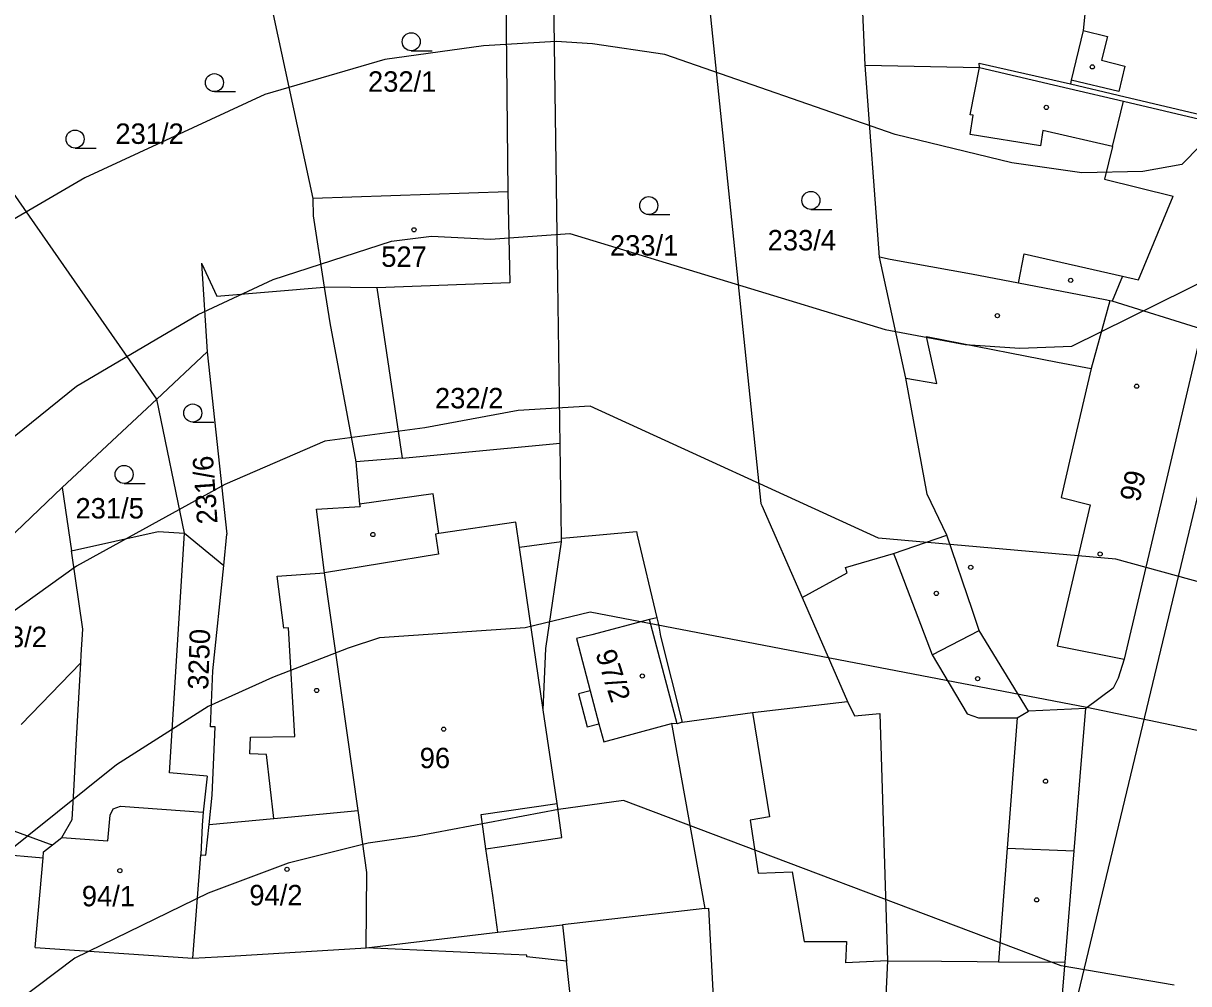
# Model space of a CAD drawing. Extents: x -555860 to -552701, y -1187050 to -1182291.
# Drawn here: x -554496.6 to -554399.7, y -1184505.6 to -1184425.7 of the extents above; entities that cross this region are included whole.
import ezdxf

# ---------------------------------------------------------------- set-up
doc = ezdxf.new("R2010")
doc.units = 0
for name, color, linetype in [('CYKLISTI_stav', 7, 'Continuous'), ('LEG_2b', 7, 'Continuous'), ('Level 25', 7, 'Continuous'), ('Level 40', 7, 'Continuous'), ('Level 41', 7, 'Continuous'), ('navrh_BV', 7, 'Continuous'), ('Poz předměty', 7, 'Continuous')]:
    doc.layers.add(name, color=color, linetype=linetype)

msp = doc.modelspace()

# ---------------------------------------------------------------- linework, layer by layer
at = {"layer": 'CYKLISTI_stav'}
for p, q in [((-554408.44, -1184426.33), (-554406.41, -1184426.85)), ((-554406.41, -1184426.85), (-554406.91, -1184428.81)), ((-554417.82, -1184433.35), (-554417.05, -1184429.41)), ((-554417.05, -1184429.41), (-554409.58, -1184431.17)), ((-554406.91, -1184428.81), (-554404.97, -1184429.3)), ((-554404.97, -1184429.3), (-554405.47, -1184431.41)), ((-554409.58, -1184431.17), (-554405.07, -1184432.23)), ((-554405.47, -1184431.41), (-554409.42, -1184430.48)), ((-554405.99, -1184436), (-554405.07, -1184432.23)), ((-554405.07, -1184432.23), (-554398.26, -1184433.83)), ((-554417.84, -1184434.99), (-554417.57, -1184433.39)), ((-554417.57, -1184433.39), (-554417.82, -1184433.35)), ((-554411.98, -1184435.93), (-554417.84, -1184434.99)), ((-554411.77, -1184434.67), (-554411.98, -1184435.93)), ((-554405.99, -1184436), (-554411.77, -1184434.67)), ((-554405.99, -1184436), (-554406.65, -1184438.71)), ((-554406.65, -1184438.71), (-554400.94, -1184440.13)), ((-554403.84, -1184447.08), (-554400.94, -1184440.13)), ((-554413.81, -1184447.35), (-554413.34, -1184444.92)), ((-554413.34, -1184444.92), (-554405.15, -1184446.78)), ((-554405.15, -1184446.78), (-554406.02, -1184448.85)), ((-554405.15, -1184446.78), (-554403.84, -1184447.08)), ((-554467.17, -1184447.74), (-554471.55, -1184447.68)), ((-554406.22, -1184448.82), (-554407.75, -1184454.46)), ((-554421.47, -1184451.8), (-554419.91, -1184452.11)), ((-554420.59, -1184455.71), (-554421.47, -1184451.8)), ((-554419.91, -1184452.11), (-554410.55, -1184453.92)), ((-554410.55, -1184453.92), (-554407.75, -1184454.46)), ((-554407.75, -1184454.46), (-554409.49, -1184461.8)), ((-554423.17, -1184455.27), (-554420.59, -1184455.71)), ((-554409.49, -1184461.8), (-554410.27, -1184465.2)), ((-554410.27, -1184465.2), (-554407.86, -1184465.79)), ((-554407.86, -1184465.79), (-554410.58, -1184477.53)), ((-554462.02, -1184468.17), (-554462.3, -1184468.23)), ((-554462.3, -1184468.23), (-554462.04, -1184469.9)), ((-554462.04, -1184469.9), (-554471.52, -1184471.45)), ((-554453.33, -1184482.86), (-554455.3, -1184469.36)), ((-554424.19, -1184469.85), (-554424.03, -1184470.27)), ((-554424.03, -1184470.27), (-554420.99, -1184478.29)), ((-554475.47, -1184471.73), (-554471.52, -1184471.45)), ((-554474.92, -1184476.07), (-554475.47, -1184471.73)), ((-554442.21, -1184484.02), (-554444.5, -1184475.35)), ((-554474.52, -1184476.02), (-554474.92, -1184476.07)), ((-554473.99, -1184485.06), (-554474.52, -1184476.02)), ((-554420.99, -1184478.29), (-554417.08, -1184476.26)), ((-554410.58, -1184477.53), (-554405.01, -1184478.65)), ((-554420.99, -1184478.29), (-554418.07, -1184483.18)), ((-554496.76, -1184484.07), (-554491.8, -1184478.94)), ((-554449.43, -1184481.26), (-554448.7, -1184484.02)), ((-554435.93, -1184483.08), (-554434.53, -1184491.76)), ((-554418.07, -1184483.18), (-554417.13, -1184483.53)), ((-554417.13, -1184483.53), (-554415.81, -1184483.52)), ((-554415.81, -1184483.52), (-554413.91, -1184483.52)), ((-554413.91, -1184483.52), (-554414.74, -1184494.37)), ((-554413.91, -1184483.52), (-554412.98, -1184482.95)), ((-554477.75, -1184486.52), (-554477.69, -1184485.12)), ((-554477.69, -1184485.12), (-554473.99, -1184485.06)), ((-554476.35, -1184486.58), (-554477.75, -1184486.52)), ((-554475.74, -1184491.88), (-554476.35, -1184486.58)), ((-554489.36, -1184491.61), (-554489.1, -1184491.1)), ((-554489.1, -1184491.1), (-554488.5, -1184490.87)), ((-554488.5, -1184490.87), (-554481.62, -1184491.37)), ((-554475.74, -1184491.88), (-554468.72, -1184491.22)), ((-554458.51, -1184491.56), (-554452.19, -1184490.64)), ((-554489.56, -1184493.76), (-554489.36, -1184491.61)), ((-554481.12, -1184492.39), (-554475.74, -1184491.88)), ((-554458.1, -1184494.4), (-554458.51, -1184491.56)), ((-554434.53, -1184491.76), (-554436.12, -1184492.02)), ((-554436.12, -1184492.02), (-554435.45, -1184496.43)), ((-554493.38, -1184493.48), (-554489.56, -1184493.76)), ((-554414.74, -1184494.37), (-554415.47, -1184503.8)), ((-554414.74, -1184494.37), (-554409.18, -1184494.58)), ((-554435.45, -1184496.43), (-554432.64, -1184496.32)), ((-554432.64, -1184496.32), (-554431.64, -1184502.12)), ((-554431.64, -1184502.12), (-554428.12, -1184502.13)), ((-554428.12, -1184502.13), (-554428.2, -1184503.91)), ((-554424.71, -1184503.73), (-554428.2, -1184503.91)), ((-554424.71, -1184503.73), (-554420.21, -1184503.76)), ((-554420.21, -1184503.76), (-554417.24, -1184503.78)), ((-554417.24, -1184503.78), (-554415.47, -1184503.8)), ((-554415.47, -1184503.8), (-554409.93, -1184503.84))]:
    msp.add_line(p, q, dxfattribs=at)
at = {"layer": 'Level 25'}
for p, q in [((-554464.312, -1184428.03), (-554462.562, -1184428.03)), ((-554480.682, -1184431.43), (-554478.932, -1184431.43)), ((-554492.272, -1184436.12), (-554490.522, -1184436.12)), ((-554444.562, -1184441.66), (-554442.812, -1184441.66)), ((-554431.072, -1184441.23), (-554429.322, -1184441.23)), ((-554482.482, -1184458.91), (-554480.732, -1184458.91)), ((-554488.192, -1184464.02), (-554486.442, -1184464.02))]:
    msp.add_line(p, q, dxfattribs=at)
for centre, radius in [((-554464.312, -1184427.28), 0.75), ((-554407.667, -1184429.369), 0.175), ((-554480.682, -1184430.68), 0.75), ((-554411.497, -1184432.739), 0.175), ((-554492.272, -1184435.37), 0.75), ((-554431.072, -1184440.48), 0.75), ((-554444.562, -1184440.91), 0.75), ((-554464.087, -1184442.919), 0.175), ((-554409.467, -1184447.129), 0.175), ((-554415.567, -1184450.059), 0.175), ((-554403.977, -1184455.929), 0.175), ((-554482.482, -1184458.16), 0.75), ((-554488.192, -1184463.27), 0.75), ((-554467.507, -1184468.269), 0.175), ((-554407.017, -1184469.889), 0.175), ((-554417.777, -1184470.999), 0.175), ((-554420.637, -1184473.169), 0.175), ((-554445.097, -1184480.039), 0.175), ((-554417.207, -1184480.259), 0.175), ((-554472.177, -1184481.239), 0.175), ((-554461.617, -1184484.459), 0.175), ((-554411.557, -1184488.789), 0.175), ((-554488.547, -1184496.229), 0.175), ((-554474.647, -1184496.119), 0.175), ((-554412.297, -1184498.659), 0.175)]:
    msp.add_circle(centre, radius, dxfattribs=at)
at = {"layer": 'Level 40'}
msp.add_lwpolyline([(-554308.641, -1184459.888), (-554329.513, -1184471.607), (-554337.832, -1184474.242), (-554350.311, -1184475.49), (-554358.631, -1184474.936), (-554366.95, -1184473.41), (-554381.006, -1184472.99), (-554393.084, -1184473.796), (-554405.698, -1184470.305), (-554425.463, -1184468.558), (-554449.443, -1184457.578), (-554455.408, -1184457.95), (-554463.178, -1184459.406), (-554471.497, -1184460.516), (-554479.817, -1184464.121), (-554492.157, -1184470.914), (-554505.746, -1184480.621), (-554525.435, -1184498.785), (-554532.09, -1184507.382)], dxfattribs=at)
at = {"layer": 'Level 41'}
for points in [[(-554397.109, -1184434.325), (-554400.228, -1184437.499), (-554403.459, -1184438.076), (-554408.547, -1184438.192), (-554414.371, -1184437.359), (-554424.077, -1184435.002), (-554443.211, -1184428.346), (-554449.225, -1184427.458), (-554452.271, -1184427.268), (-554458.301, -1184427.612), (-554466.506, -1184428.763), (-554476.489, -1184431.675), (-554491.464, -1184438.607), (-554498.12, -1184442.49)], [(-554544.569, -1184498.231), (-554492.157, -1184455.939), (-554482.035, -1184449.978), (-554475.795, -1184447.066), (-554465.962, -1184443.853), (-554462.623, -1184443.46), (-554457.712, -1184443.688), (-554451.121, -1184443.218), (-554424.909, -1184451.226), (-554418.253, -1184452.474), (-554413.689, -1184452.763), (-554409.379, -1184452.613), (-554397.378, -1184446.677), (-554380.18, -1184451.51), (-554376.297, -1184451.51), (-554358.631, -1184453.166), (-554352.472, -1184453.422), (-554345.874, -1184453.306), (-554337, -1184451.502), (-554330.345, -1184449.284), (-554317.033, -1184443.044), (-554305.134, -1184437.012), (-554296.376, -1184433.98), (-554286.074, -1184428.758)], [(-554281.388, -1184467.612), (-554288.193, -1184469.666), (-554305.802, -1184474.242), (-554333.672, -1184484.78), (-554357.521, -1184491.021), (-554364.022, -1184491.538), (-554368.614, -1184491.436), (-554375.547, -1184490.05), (-554387.716, -1184486.416), (-554396.573, -1184485.072), (-554408.113, -1184482.656), (-554449.443, -1184474.735), (-554454.849, -1184476.041), (-554466.952, -1184476.854), (-554469.556, -1184477.709), (-554475.863, -1184480.154), (-554481.203, -1184482.563), (-554488.829, -1184487.415), (-554511.153, -1184505.302), (-554515.313, -1184509.6)], [(-554400.867, -1184505.748), (-554410.26, -1184504.136), (-554446.647, -1184490.402), (-554452.053, -1184491.148), (-554463.817, -1184493.353), (-554467.892, -1184493.931), (-554474.548, -1184495.596), (-554481.203, -1184498.092), (-554492.296, -1184503.498), (-554505.191, -1184513.204)]]:
    msp.add_lwpolyline(points, dxfattribs=at)
at = {"layer": 'navrh_BV'}
for p, q in [((-554407.09, -1184412.86), (-554408.44, -1184426.33)), ((-554477.89, -1184415.35), (-554472.51, -1184440.32)), ((-554456.48, -1184419.6), (-554456.27, -1184439.75)), ((-554452.12, -1184447.23), (-554452.51, -1184419.74)), ((-554439.93, -1184420.21), (-554435.24, -1184465.69)), ((-554426.57, -1184429.22), (-554426.75, -1184424.83)), ((-554408.44, -1184426.33), (-554409.42, -1184430.48)), ((-554485.48, -1184457), (-554504.94, -1184429.06)), ((-554426.57, -1184429.22), (-554417.05, -1184429.41)), ((-554425.37, -1184445.21), (-554426.57, -1184429.22)), ((-554417.09, -1184429.07), (-554409.49, -1184430.78)), ((-554417.05, -1184429.41), (-554417.09, -1184429.07)), ((-554409.42, -1184430.48), (-554409.49, -1184430.78)), ((-554409.49, -1184430.78), (-554405.53, -1184431.71)), ((-554405.53, -1184431.71), (-554398.11, -1184433.47)), ((-554456.27, -1184439.75), (-554472.51, -1184440.32)), ((-554456.27, -1184439.75), (-554456.1, -1184447.34)), ((-554472.51, -1184440.32), (-554472.48, -1184441.75)), ((-554472.48, -1184441.75), (-554471.55, -1184447.68)), ((-554481.77, -1184445.69), (-554480.48, -1184448.43)), ((-554481.77, -1184445.69), (-554481.3, -1184453.08)), ((-554424.47, -1184445.38), (-554425.37, -1184445.21)), ((-554423.17, -1184455.27), (-554425.37, -1184445.21)), ((-554417.71, -1184446.6), (-554424.47, -1184445.38)), ((-554413.81, -1184447.35), (-554417.71, -1184446.6)), ((-554480.48, -1184448.43), (-554471.55, -1184447.68)), ((-554471.55, -1184447.68), (-554471.08, -1184450.66)), ((-554456.1, -1184447.34), (-554467.17, -1184447.74)), ((-554467.17, -1184447.74), (-554465.07, -1184461.92)), ((-554451.82, -1184468.57), (-554452.12, -1184447.23)), ((-554406.6, -1184448.74), (-554413.81, -1184447.35)), ((-554406.22, -1184448.82), (-554406.6, -1184448.74)), ((-554406.02, -1184448.85), (-554406.22, -1184448.82)), ((-554398.55, -1184451.19), (-554406.02, -1184448.85)), ((-554471.08, -1184450.66), (-554468.93, -1184462.21)), ((-554398.55, -1184451.19), (-554401.38, -1184463.21)), ((-554395.77, -1184451.89), (-554411.1, -1184515.83)), ((-554481.3, -1184453.08), (-554485.48, -1184457)), ((-554481.3, -1184453.08), (-554479.66, -1184468.23)), ((-554421.4, -1184464.92), (-554423.17, -1184455.27)), ((-554493.34, -1184464.37), (-554485.48, -1184457)), ((-554483.16, -1184468.16), (-554485.48, -1184457)), ((-554465.07, -1184461.92), (-554468.93, -1184462.21)), ((-554468.93, -1184462.21), (-554468.63, -1184465.74)), ((-554401.38, -1184463.21), (-554405.01, -1184478.65)), ((-554498.52, -1184469.28), (-554493.34, -1184464.37)), ((-554493.34, -1184464.37), (-554492.58, -1184469.63)), ((-554462.49, -1184464.88), (-554468.63, -1184465.74)), ((-554462.02, -1184468.17), (-554462.49, -1184464.88)), ((-554419.77, -1184468.31), (-554421.4, -1184464.92)), ((-554472.2, -1184466.16), (-554468.55, -1184465.93)), ((-554471.52, -1184471.45), (-554472.2, -1184466.16)), ((-554468.63, -1184465.74), (-554468.55, -1184465.93)), ((-554435.24, -1184465.69), (-554435.15, -1184465.86)), ((-554435.15, -1184465.86), (-554431.8, -1184473.51)), ((-554455.61, -1184467.24), (-554462.02, -1184468.17)), ((-554455.3, -1184469.36), (-554455.61, -1184467.24)), ((-554492.58, -1184469.63), (-554485.36, -1184468.02)), ((-554485.36, -1184468.02), (-554483.16, -1184468.16)), ((-554484.42, -1184488.1), (-554483.16, -1184468.16)), ((-554483.16, -1184468.16), (-554479.89, -1184470.85)), ((-554451.12, -1184468.51), (-554445.58, -1184468.02)), ((-554445.58, -1184468.02), (-554445.51, -1184468.31)), ((-554479.89, -1184470.85), (-554479.66, -1184468.23)), ((-554451.82, -1184468.87), (-554455.3, -1184469.36)), ((-554453.13, -1184477.76), (-554451.82, -1184468.87)), ((-554451.82, -1184468.57), (-554451.12, -1184468.51)), ((-554451.82, -1184468.87), (-554451.82, -1184468.57)), ((-554445.51, -1184468.31), (-554443.9, -1184475.19)), ((-554424.19, -1184469.85), (-554419.77, -1184468.31)), ((-554417.64, -1184474.6), (-554419.77, -1184468.31)), ((-554491.64, -1184476.13), (-554492.58, -1184469.63)), ((-554428.2, -1184471.01), (-554424.19, -1184469.85)), ((-554480.81, -1184479.61), (-554479.89, -1184470.85)), ((-554428.07, -1184471.45), (-554428.2, -1184471.01)), ((-554468.72, -1184491.22), (-554471.52, -1184471.45)), ((-554431.8, -1184473.51), (-554428.07, -1184471.45)), ((-554431.8, -1184473.51), (-554428.02, -1184482.16)), ((-554417.08, -1184476.26), (-554417.64, -1184474.6)), ((-554444.5, -1184475.35), (-554449.3, -1184476.6)), ((-554443.9, -1184475.19), (-554444.5, -1184475.35)), ((-554443.9, -1184475.19), (-554443.79, -1184475.63)), ((-554443.79, -1184475.63), (-554443.69, -1184476.07)), ((-554491.76, -1184478.28), (-554491.64, -1184476.13)), ((-554449.3, -1184476.6), (-554450.57, -1184476.92)), ((-554450.57, -1184476.92), (-554449.43, -1184481.26)), ((-554443.69, -1184476.07), (-554443.57, -1184476.72)), ((-554443.57, -1184476.72), (-554441.78, -1184483.87)), ((-554412.98, -1184482.95), (-554417.08, -1184476.26)), ((-554453.33, -1184482.86), (-554453.13, -1184477.76)), ((-554491.8, -1184478.94), (-554491.76, -1184478.28)), ((-554405.01, -1184478.65), (-554405.53, -1184480.23)), ((-554492.17, -1184485.75), (-554491.8, -1184478.94)), ((-554481.01, -1184484.26), (-554480.81, -1184479.61)), ((-554405.53, -1184480.23), (-554405.93, -1184481.06)), ((-554449.43, -1184481.26), (-554450.4, -1184481.51)), ((-554450.4, -1184481.51), (-554449.67, -1184484.27)), ((-554405.93, -1184481.06), (-554408.21, -1184482.75)), ((-554435.93, -1184483.08), (-554428.02, -1184482.16)), ((-554428.02, -1184482.16), (-554427.45, -1184483.35)), ((-554408.21, -1184482.75), (-554412.98, -1184482.95)), ((-554408.59, -1184487.36), (-554408.21, -1184482.75)), ((-554452.19, -1184490.64), (-554453.33, -1184482.86)), ((-554441.78, -1184483.87), (-554435.93, -1184483.08)), ((-554427.45, -1184483.35), (-554425.35, -1184483.16)), ((-554425.35, -1184483.16), (-554424.71, -1184503.73)), ((-554480.61, -1184484.27), (-554481.01, -1184484.26)), ((-554480.86, -1184489.95), (-554480.61, -1184484.27)), ((-554449.67, -1184484.27), (-554448.7, -1184484.02)), ((-554448.7, -1184484.02), (-554448.3, -1184485.52)), ((-554448.3, -1184485.52), (-554442.67, -1184483.99)), ((-554442.67, -1184483.99), (-554439.89, -1184499.37)), ((-554442.21, -1184484.02), (-554442.67, -1184483.99)), ((-554441.78, -1184483.87), (-554442.21, -1184484.02)), ((-554492.36, -1184489.12), (-554492.17, -1184485.75)), ((-554409.18, -1184494.58), (-554408.59, -1184487.36)), ((-554481.28, -1184488.38), (-554484.42, -1184488.1)), ((-554481.28, -1184488.38), (-554481.62, -1184491.37)), ((-554492.52, -1184491.97), (-554492.36, -1184489.12)), ((-554481.12, -1184492.39), (-554480.86, -1184489.95)), ((-554481.62, -1184491.37), (-554481.69, -1184492.44)), ((-554468, -1184496.38), (-554468.72, -1184491.22)), ((-554451.78, -1184493.48), (-554452.19, -1184490.64)), ((-554500.03, -1184491.96), (-554494.42, -1184493.99)), ((-554493.38, -1184493.48), (-554492.52, -1184491.97)), ((-554481.69, -1184492.44), (-554481.8, -1184494.9)), ((-554481.4, -1184494.94), (-554481.12, -1184492.39)), ((-554504.44, -1184494.32), (-554494.94, -1184495.16)), ((-554494.9, -1184494.65), (-554494.16, -1184494.08)), ((-554494.42, -1184493.99), (-554494.16, -1184494.08)), ((-554494.16, -1184494.08), (-554493.38, -1184493.48)), ((-554458.1, -1184494.4), (-554455.83, -1184494.07)), ((-554455.83, -1184494.07), (-554451.78, -1184493.48)), ((-554495.6, -1184502.63), (-554494.94, -1184495.16)), ((-554494.94, -1184495.16), (-554494.9, -1184494.65)), ((-554482.49, -1184503.52), (-554481.8, -1184494.9)), ((-554481.8, -1184494.9), (-554481.4, -1184494.94)), ((-554457.54, -1184498.3), (-554458.1, -1184494.4)), ((-554409.93, -1184503.84), (-554409.18, -1184494.58)), ((-554468.05, -1184502.66), (-554468, -1184496.38)), ((-554457.1, -1184501.34), (-554457.54, -1184498.3)), ((-554439.89, -1184499.37), (-554439.59, -1184499.35)), ((-554439.59, -1184499.35), (-554438.92, -1184512.28)), ((-554468.05, -1184502.66), (-554457.1, -1184501.34)), ((-554495.6, -1184502.63), (-554482.49, -1184503.52)), ((-554479.39, -1184503.34), (-554468.05, -1184502.66)), ((-554455.99, -1184503.2), (-554468.05, -1184502.66)), ((-554482.49, -1184503.52), (-554479.39, -1184503.34)), ((-554454.7, -1184503.26), (-554455.99, -1184503.2)), ((-554454.7, -1184503.41), (-554454.7, -1184503.26)), ((-554451.39, -1184503.77), (-554454.7, -1184503.41)), ((-554450.15, -1184515.14), (-554451.39, -1184503.77)), ((-554424.71, -1184503.73), (-554425.04, -1184511.26)), ((-554410.64, -1184512.52), (-554409.93, -1184503.84))]:
    msp.add_line(p, q, dxfattribs=at)
at = {"layer": 'Poz předměty'}
for points in [[(-554465.07, -1184461.92), (-554451.931, -1184460.67)], [(-554439.89, -1184499.37), (-554451.722, -1184500.724)], [(-554457.1, -1184501.34), (-554451.722, -1184500.724), (-554451.39, -1184503.77)]]:
    msp.add_lwpolyline(points, dxfattribs=at)

# ---------------------------------------------------------------- texts
at = {"layer": 'LEG_2b'}
for s, p in [('232/1', (-554467.91, -1184431.435)), ('231/2', (-554488.92, -1184435.775)), ('233/4', (-554434.67, -1184444.635)), ('233/1', (-554447.79, -1184445.065)), ('527', (-554466.81, -1184446.005)), ('232/2', (-554462.34, -1184457.775)), ('231/5', (-554492.24, -1184466.935)), ('93/2', (-554499.04, -1184477.635)), ('96', (-554463.61, -1184487.705)), ('94/1', (-554491.71, -1184499.195)), ('94/2', (-554477.78, -1184499.115))]:
    msp.add_text(s, height=1.7, dxfattribs=at).set_placement(p)
for s, rotation, p in [('231/6', 94, (-554480.416, -1184467.34)), ('99', 77, (-554403.755, -1184465.635)), ('3250', 88, (-554481.203, -1184481.204)), ('97/2', 288, (-554449.014, -1184478.151))]:
    msp.add_text(s, height=1.7, rotation=rotation, dxfattribs=at).set_placement(p)

doc.saveas('drawing.dxf')
